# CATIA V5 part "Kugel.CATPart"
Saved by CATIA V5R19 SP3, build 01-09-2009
Part number: Kugel
Bounding box of the stored display mesh (mm): x 0 to 100, y -100 to 0, z 0 to 100
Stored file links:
  C:\Documents and Settings\uwe.duda\My Documents\Temp\Netzer\Kugel.CATPart
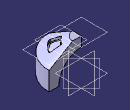
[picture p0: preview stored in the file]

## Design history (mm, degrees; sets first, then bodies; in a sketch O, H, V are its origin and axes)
Set1
  Plane1: type Angle, RefPlane zx-plane, Direction edge [face of Shaft1 | face of Shaft1], Angle 45
  Sketch1 on Plane1, origin (0, 0, 0), H (-0.7071, 0.7071, 0), V (0, 0, 1)
    line L1 (0, 270) -> (0, 100)
    axis line L2 (0, 100) -> (130, 100)
    reference projected line E1 (0, 100) -> (-411.0742, 100) from edge [face of Shaft1 from Sketch3.L3 | face of Shaft1]
    vertical: L1 V
    horizontal: L2 H
    coincidence: L2 E1, L1 V
  Sketch2 on Plane1, origin (0, 0, 0), H (-0.7071, 0.7071, 0), V (0, 0, 1)
    line L1 (-45, 89.4893) -> (-45, 79.4893)
    point P1 (-45, 89.4893)
    arc A1 centre (-6.724, -12.8955) radius 100 from (-75, 60.1688) to (-45, 79.4893) cw
    projected line E1 (-26.7949, 100) -> (-100, 57.735) from face of Shaft1 from Sketch3.L5
    construction line L2 (-60, 89.4893) -> (-60, 71.7311)
    point P8 (-60, 71.7311)
    axis line L3 (0, 100) -> (0, -20.8257)
    point P9 (0, 100)
    line L4 (-75, 72.1688) -> (-45, 89.4893)
    point P11 (-75, 72.1688)
    line L5 (-75, 60.1688) -> (-75, 72.1688)
    radius A1 = 100
    distance L2 V = 60
    length L1 = 10
    distance L1 L5 = 30
    length L5 = 12
    vertical: L1 V, L2 V, L3 V, L5 V
    coincidence: P1 E1, P8 A1, P9 V, P11 E1
    parallelism: L4 E1
    symmetry: L5 L1 L2
  Plane2: type Offset, RefPlane face of Shaft1 from Sketch3.L3, Offset 10, reversed
  Point1: type OnCurve, Support edge [face of Shaft1 from Sketch3.L5 | face of Groove1 from Sketch2.L1], Ratio 0.5
  Plane3: type OffsetPt, RefPlane face of Shaft1 from Sketch3.L3, RefPoint Point1
  Point2: type OnCurve, Support edge [face of Groove1 from Sketch2.A1 | face of Fillet1], Ratio 0.5
  Plane4: type OffsetPt, RefPlane face of Shaft1 from Sketch3.L3, RefPoint Point2
Body1 (main body)
  Sketch3 on yz-plane, origin (0, 0, 0), H (0, 1, 0), V (0, 0, 1)
    arc A1 centre (0, 0) radius 70 from (0, 70) to (-70, 0) ccw
    point P1 (-70, 0)
    point P2 (0, 70)
    line L1 (-70, 0) -> (-100, 0)
    line L2 (0, 70) -> (0, 100)
    line L3 (0, 100) -> (-26.7949, 100)
    line L4 (-100, 0) -> (-100, 57.735)
    line L5 (-100, 57.735) -> (-26.7949, 100)
    axis line L6 (0, 0) -> (0, 750)
    radius A1 = 70
    distance L3 H = 100
    distance L4 V = 100
    distance L5 O = 100
    angle L5 L3 = 30
    coincidence: P1 H, P2 V
    horizontal: L1 H, L3 H
    vertical: L2 V, L4 V, L6 V
  Shaft1: profile Sketch3, axis Sketch3.L6, angle 90
  Groove1: profile Sketch2, axis Sketch2.L3, angle 20, second angle 20
  Fillet1: radius 2, on edge [face of Groove1 from Sketch2.L1 | face of Groove1]; edge [face of Groove1 from Sketch2.L5 | face of Groove1]; edge [face of Groove1 | face of Groove1 from Sketch2.L1]; edge [face of Groove1 | face of Groove1 from Sketch2.L5]; edge [face of Groove1 | face of Groove1 from Sketch2.A1]; edge [face of Groove1 from Sketch2.L1 | face of Groove1 from Sketch2.A1]; edge [face of Groove1 from Sketch2.A1 | face of Groove1]; edge [face of Groove1 from Sketch2.A1 | face of Groove1 from Sketch2.L5]
Body2 "Rohmat"
  Shaft2: profile Sketch2, axis Sketch2.L3, angle 20, second angle 20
